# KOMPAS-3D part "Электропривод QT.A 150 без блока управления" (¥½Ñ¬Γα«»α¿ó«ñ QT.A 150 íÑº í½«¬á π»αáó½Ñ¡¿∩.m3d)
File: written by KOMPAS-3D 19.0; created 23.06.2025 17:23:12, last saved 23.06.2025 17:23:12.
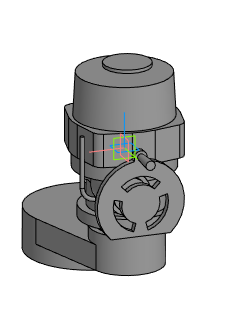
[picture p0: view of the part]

Document properties: Автор: Евгений; Полное имя файла: E:\Dendor Работа Сачек\3D для проектировщиков\3.5 Тип QT.А Электропривод\stp_Электропривод QT.A без блока управления\Электропривод QT.A 150 без блока управления.m3d

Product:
- Part/product: Электропривод QT.A 150 без блока управления

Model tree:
1. Операция без истории:1  (labels: Электропривод QT.A 150 без блока управления)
